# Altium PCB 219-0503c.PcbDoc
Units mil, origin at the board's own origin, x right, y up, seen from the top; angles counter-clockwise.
Board outline 5500 x 3800 mil, 2 copper layers (Top Layer, Bottom Layer); 110 components, 92 nets, 333 pads, 65 vias.
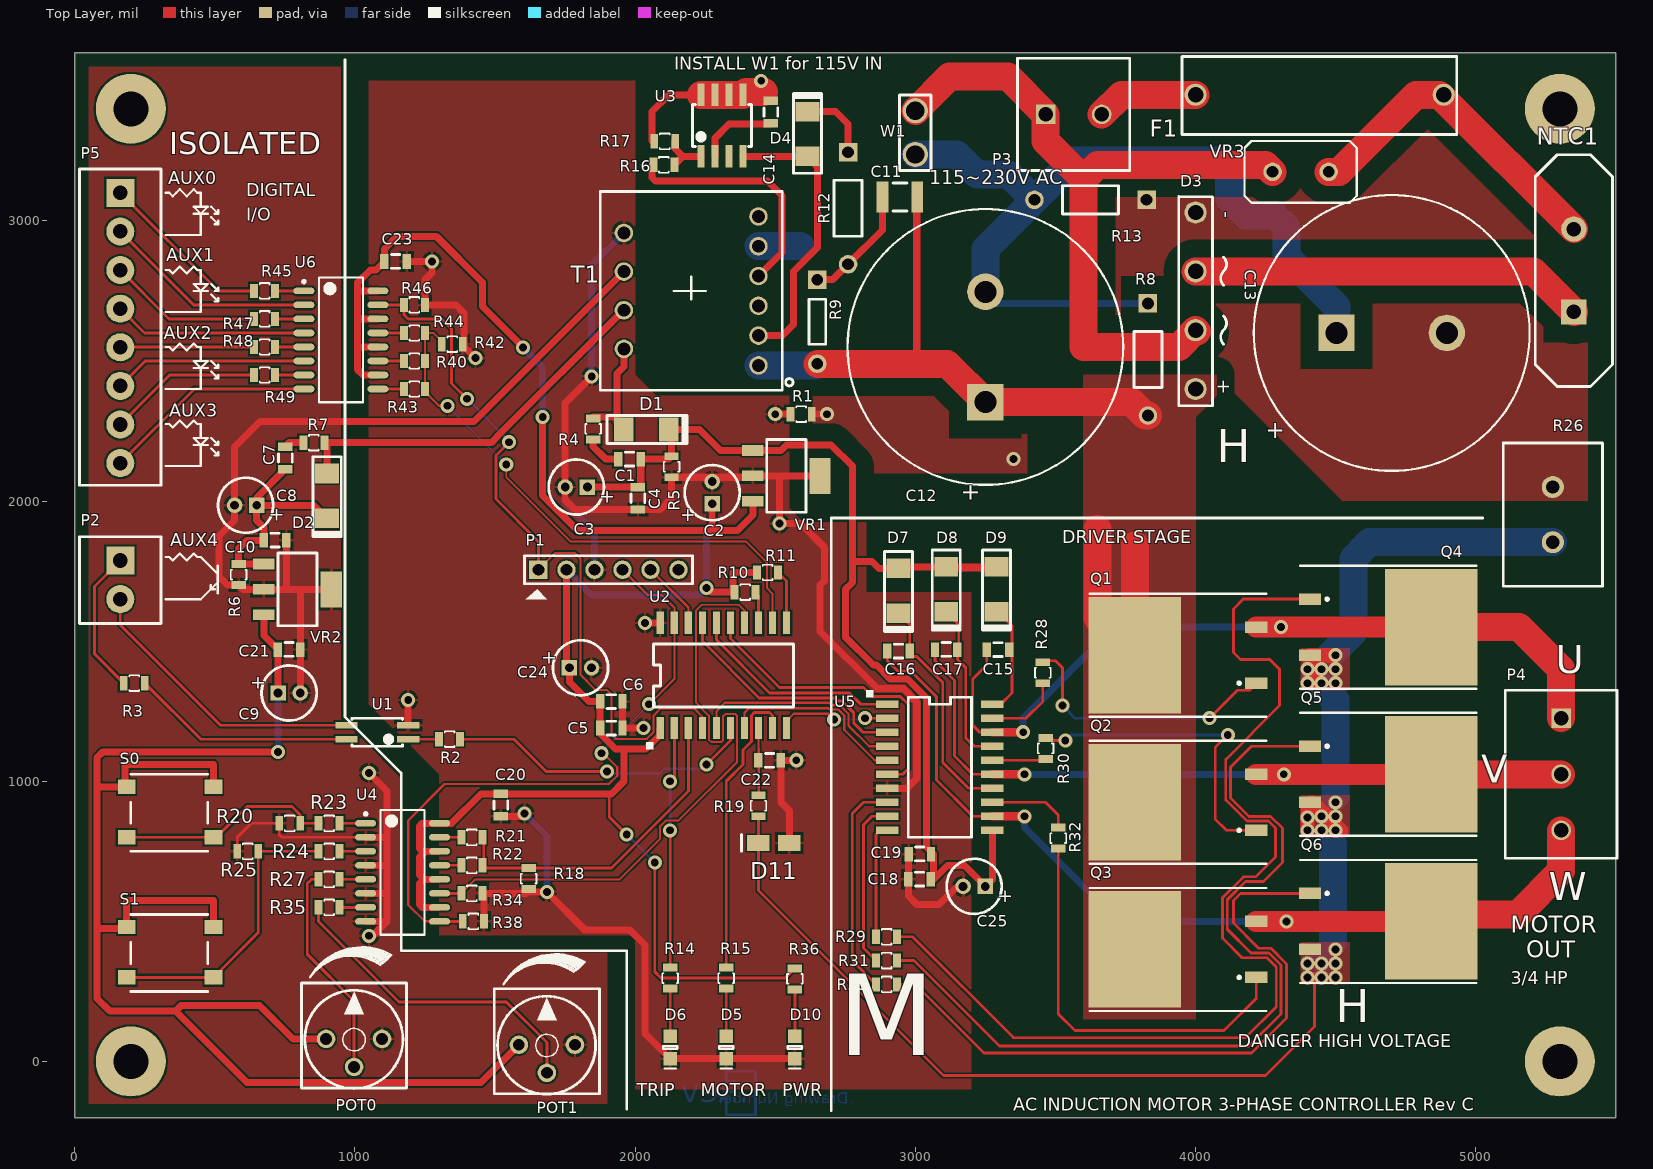
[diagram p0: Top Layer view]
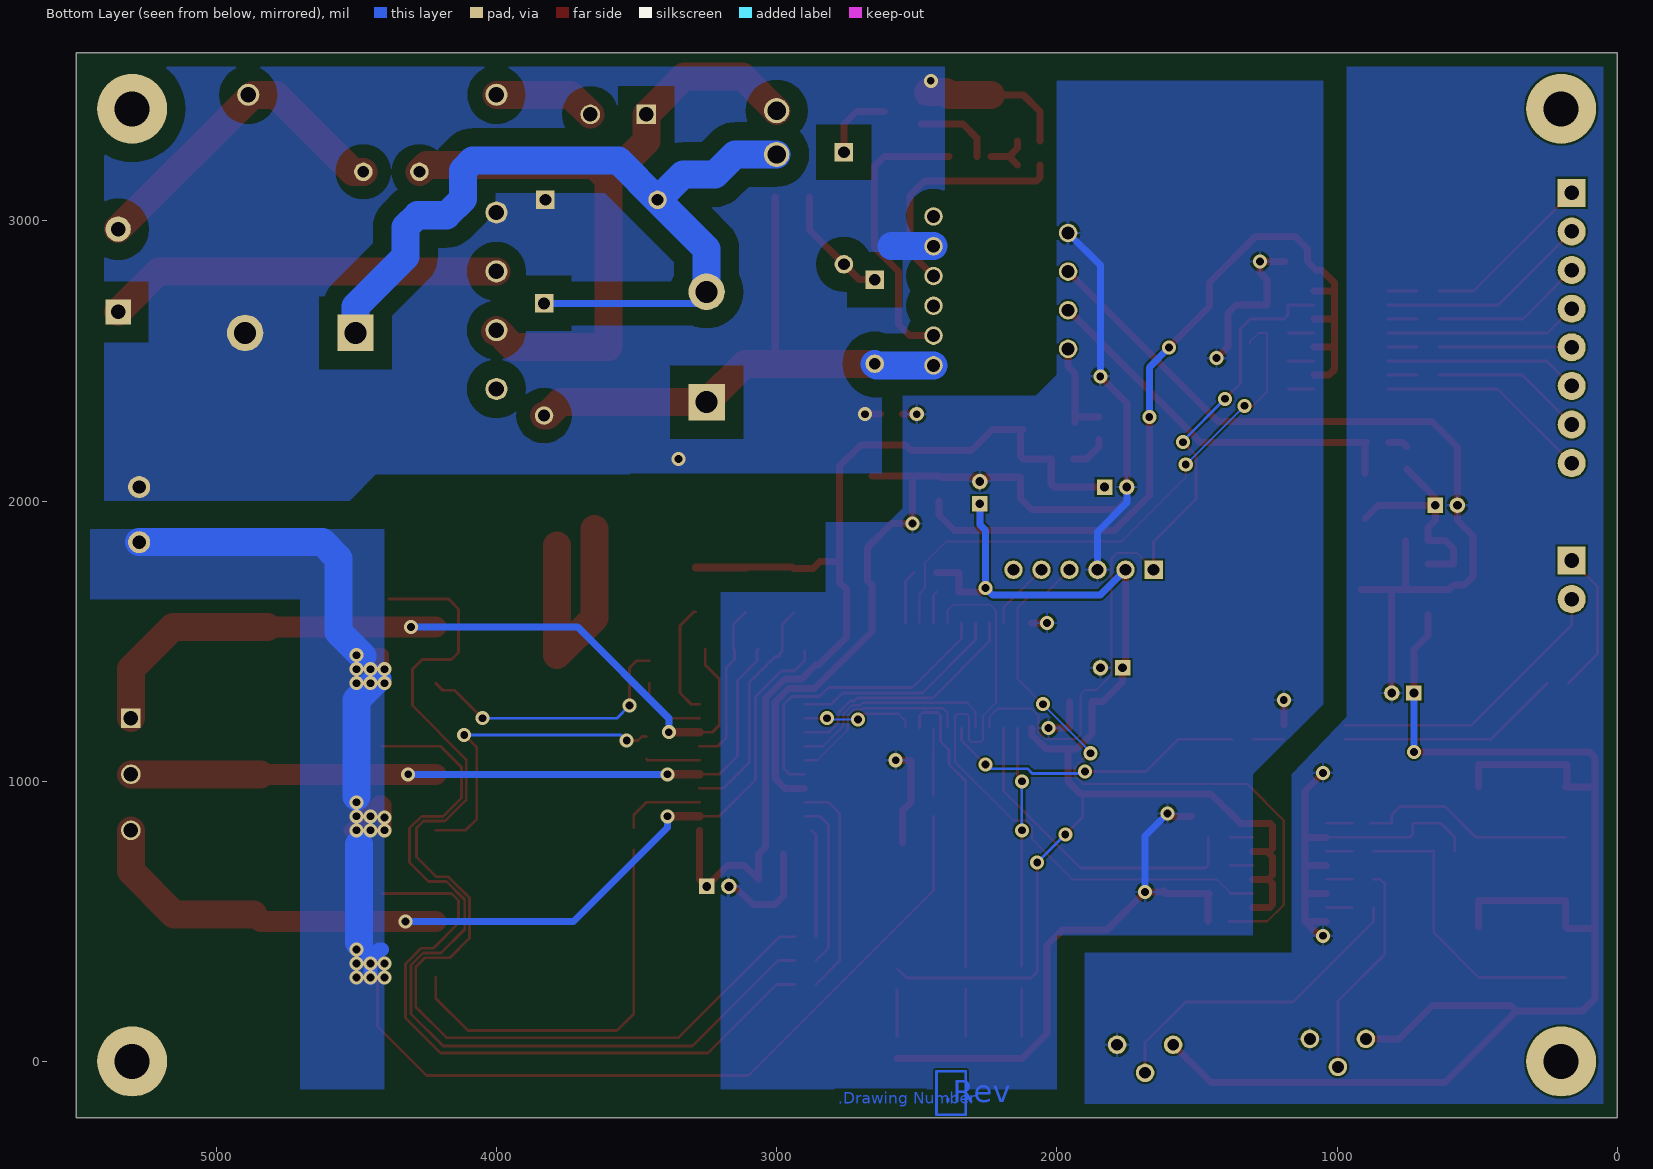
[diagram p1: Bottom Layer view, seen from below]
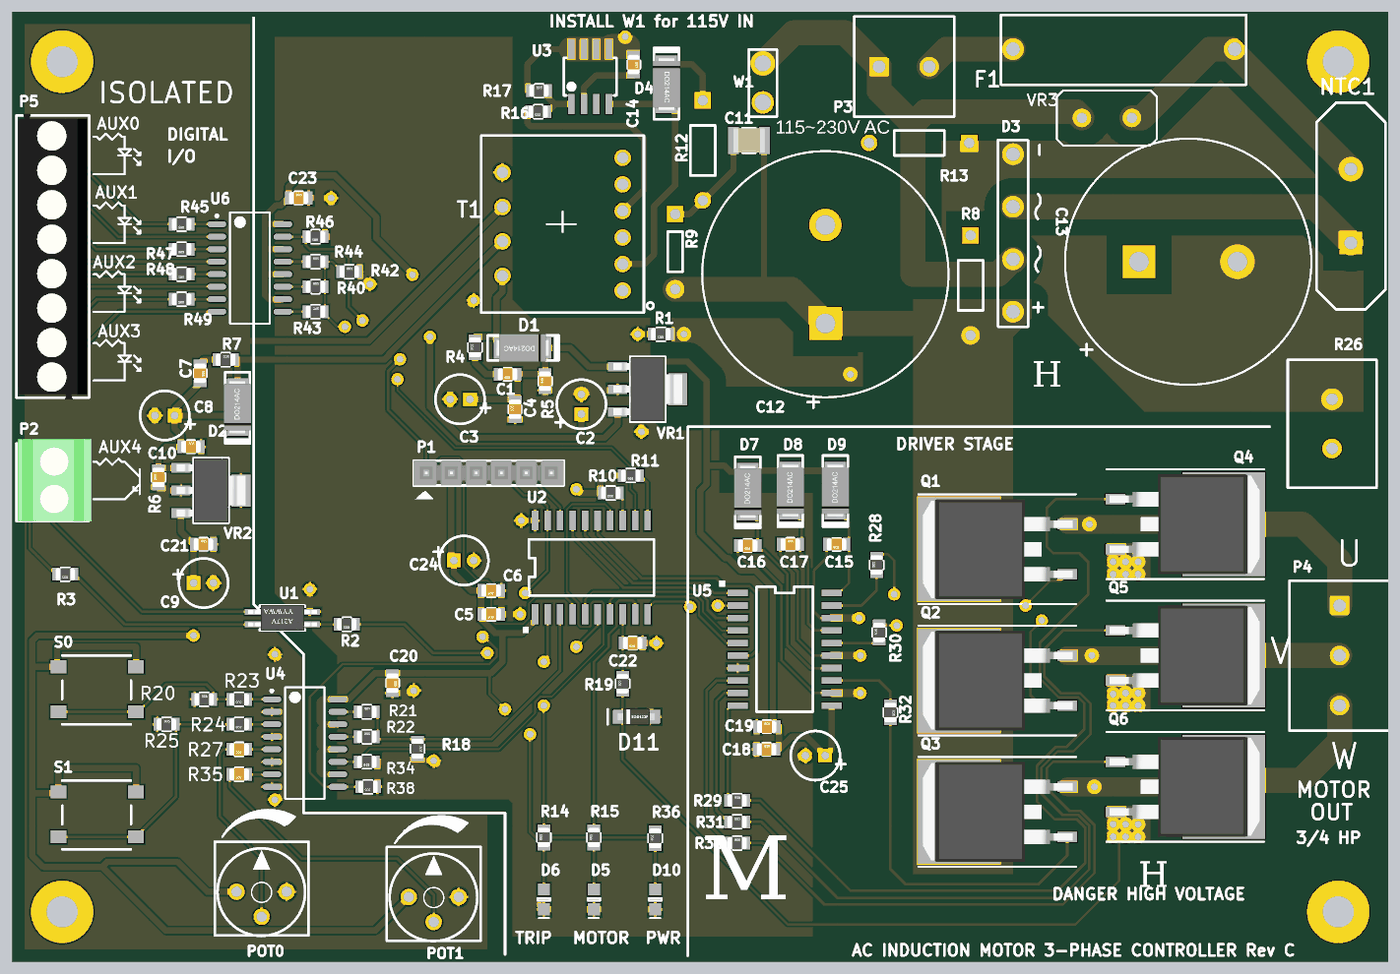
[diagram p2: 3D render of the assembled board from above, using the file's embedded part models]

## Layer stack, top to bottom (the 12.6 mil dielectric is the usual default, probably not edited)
Top Layer: signal copper 1.4
Dielectric: dielectric 12.6, FR-4, Dk 4.8
Bottom Layer: signal copper 1.4

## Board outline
0,-200 5500,-200 5500,3600 0,3600

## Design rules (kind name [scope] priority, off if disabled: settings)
Clearance Clearance_4 [InNamedPolygon('Top Layer-AGND')] p1: gap=65
Clearance Clearance_3 [InNamedPolygon('Bottom Layer-AGND')] p2: gap=65
Clearance [All] p3: gap=7
FabricationTestPointUsage TestPointUsage [All] p1: valid=0 allowmultiple=FALSE
FabricationTestpoint Testpoint [All] p1: side=3 testpointundercomponent=TRUE minsize=40 maxsize=100 preferedsize=60 minholesize=0 maxholesize=40 preferedholesize=32 testpointgrid=1 allowsidetop=TRUE allowsidebottom=TRUE usegrid=TRUE gridtolerance=0.01
HoleSize [All] p1: absolutevalues=TRUE maxlimit=125 minlimit=1 maxpercent=80.000 minpercent=20.000
PolygonConnect PolygonConnect_12 [All vs IsNamedPolygon('Top Layer-AGND')] p1: connectstyle=Direct reliefconductorwidth=10 reliefentries=4 polygonreliefangle="90 Angle" airgapwidth=10
PolygonConnect PolygonConnect_11 [All vs IsNamedPolygon('Bottom Layer-AGND')] p2: connectstyle=Direct reliefconductorwidth=10 reliefentries=4 polygonreliefangle="90 Angle" airgapwidth=10
PolygonConnect PolygonConnect_5 [All vs IsNamedPolygon('Top Layer-NetQ4_3')] p3: connectstyle=Direct reliefconductorwidth=10 reliefentries=4 polygonreliefangle="90 Angle" airgapwidth=10
PolygonConnect PolygonConnect_4 [All vs IsNamedPolygon('Top Layer-+VBUS')] p4: connectstyle=Direct reliefconductorwidth=10 reliefentries=4 polygonreliefangle="90 Angle" airgapwidth=10
PolygonConnect PolygonConnect_3 [All vs IsNamedPolygon('Top Layer-+VBUS')] p5: connectstyle=Direct reliefconductorwidth=10 reliefentries=4 polygonreliefangle="90 Angle" airgapwidth=10
PolygonConnect PolygonConnect_2 [All vs IsNamedPolygon('Bottom Layer-+VBUS')] p6: connectstyle=Direct reliefconductorwidth=10 reliefentries=4 polygonreliefangle="90 Angle" airgapwidth=10
PolygonConnect PolygonConnect_1 [All vs IsNamedPolygon('Bottom Layer-NetQ4_3')] p7: connectstyle=Direct reliefconductorwidth=10 reliefentries=4 polygonreliefangle="90 Angle" airgapwidth=10
PolygonConnect PolygonConnect_10 [All vs IsNamedPolygon('Bottom Layer-NetQ4_3')] p8: connectstyle=Direct reliefconductorwidth=10 reliefentries=4 polygonreliefangle="90 Angle" airgapwidth=10
PolygonConnect PolygonConnect_9 [All vs IsNamedPolygon('Bottom Layer-+VBUS')] p9: connectstyle=Direct reliefconductorwidth=10 reliefentries=4 polygonreliefangle="90 Angle" airgapwidth=10
PolygonConnect PolygonConnect_8 [All vs IsNamedPolygon('Bottom Layer-+VBUS')] p10: connectstyle=Direct reliefconductorwidth=10 reliefentries=4 polygonreliefangle="90 Angle" airgapwidth=10
PolygonConnect PolygonConnect_7 [All vs IsNamedPolygon('Top Layer-+VBUS')] p11: connectstyle=Direct reliefconductorwidth=10 reliefentries=4 polygonreliefangle="90 Angle" airgapwidth=10
PolygonConnect PolygonConnect_6 [All vs IsNamedPolygon('Bottom Layer-Net 1')] p12: connectstyle=Relief reliefconductorwidth=10 reliefentries=4 polygonreliefangle="90 Angle" airgapwidth=10
PolygonConnect [All] p13: connectstyle=Relief reliefconductorwidth=10 reliefentries=4 polygonreliefangle="90 Angle" airgapwidth=10
RoutingVias [All] p1: holewidth=28 width=50 viastyle="Through Hole" minholewidth=28 minwidth=50 maxholewidth=28 maxwidth=50
SilkToSolderMaskClearance SilkscreenOverComponentPads [IsPad] p1: minsilkscreentomaskgap=10 clearancetoexposedcopper=TRUE
SolderMaskExpansion [All] p1: expansion=4
Width [All] p1: maxlimit=100 minlimit=6 preferedwidth=10
24 further rules are at their usual default settings.

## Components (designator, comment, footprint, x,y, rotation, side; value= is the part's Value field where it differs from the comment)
C1 "CAP0805_470pF" CAP_0805 1980,2150 r180 top
C2 "UVZ1E100MDD" CAP079in_5mm 2275,2030 r90 top
C3 "ESH476M035AE3AA" CAP079in_5mm 1790,2050 r180 top
C4 "CAP0805_0.1uF_50V" CAP_0805 2010,2010 r90 top
C5 "CAP0805_0.1uF_50V" CAP_0805 1915,1190 r180 top
C6 "CAP0805_1uF" CAP_0805 1915,1285 r180 top
C7 "CAP0805_470pF" CAP_0805 751,2154 r270 top
C8 "ESH476M035AE3AA" CAP079in_5mm 610,1985 r180 top
C9 "UVZ1E100MDD" CAP079in_5mm 765,1315 r0 top
C10 "CAP0805_0.1uF_50V" CAP_0805 715,1860 r0 top
C11 "CAP1210_820pF" CAP_1210 2945,3085 r0 top
C12 "CAP_560uF_250V" CAPPRS10-25x50 3250,2550 r90 top
C13 "CAP_560uF_250V" CAPPRS10-25x50 4700,2600 r0 top
C14 "CAP0805_1uF" CAP_0805 2484,3388 r270 top
C15 "CAP0805_1uF" CAP_0805 3295,1470 r180 top
C16 "CAP0805_1uF" CAP_0805 2940,1465 r180 top
C17 "CAP0805_1uF" CAP_0805 3110,1470 r0 top
C18 "CAP0805_0.1uF_50V" CAP_0805 3015,650 r0 top
C19 "CAP0805_1uF" CAP_0805 3016,740 r0 top
C20 "CAP0805_1uF" CAP_0805 1520,915 r270 top
C21 "CAP0805_1uF" CAP_0805 765,1470 r0 top
C22 "CAP0805_1uF" CAP_0805 2480,1075 r180 top
C23 "CAP0805_1uF" CAP_0805 1145,2855 r0 top
C24 "UVZ1E100MDD" CAP079in_5mm 1805,1405 r0 top
C25 "UVZ1E100MDD" CAP079in_5mm 3210,625 r180 top
D1 "DIODE-SMA_STTH1L06A" DIODE-SMA 2120,2255 r270 top
D2 "DIODE-SMA_STTH1L06A" DIODE-SMA 900.79,1938.29 r180 top
D3 "Bridge1" DiodeBridge 4000,2400 r90 top
D4 "DIODE-SMA_STTH1L06A" DIODE-SMA 2615,3390 r0 top
D5 "LED2" LED_0805_RED 2325,50 r90 top
D6 "LED2" LED_0805_GRN 2125,50 r90 top
D7 "DIODE-SMA_STTH1L06A" DIODE-SMA 2940,1600 r180 top
D8 "DIODE-SMA_STTH1L06A" DIODE-SMA 3110,1605 r180 top
D9 "DIODE-SMA_STTH1L06A" DIODE-SMA 3290,1605 r180 top
D10 "LED2" LED_0805_GRN 2570.01,50 r90 top
D11 "CFRMT107-HF" TC3216 2550,780 r180 top
F1 "Fuse 2" FuseSocketHolder 4000,3450 r0 top
NTC1 "MF72-010D11" THERM_NTC_7.5MM_THERM_NTC_7.5MM(Primary) 5350,2675 r90 top
P1 "PICKIT2" TERMSTRIP_TSW-106-07-F-S 1905,1755 r0 top
P2 "ED555/2DS" "TERM BLOCK, 2POS, 3.81.mm" 162.5,1787.8 r0 top
P3 "OSTTC022162" 2PHDR-200 3465,3380 r90 top
P4 "EDZ350/3" 3PHDRX200 5305,1225 r0 top
P5 "Term_BLK_8pos 3.5mm" "TERM BLOCK, 8POS, 3.5mm" 162.5,3100 r0 top
POT0 "3386P-1-202TLF" POT3386P-1-XXXT 897,-107 r0 top
POT1 "3386P-1-202TLF" POT3386P-1-XXXT 1585,-128 r0 top
Q1 "IRG4BC20KD-S_1" D2PAK 4000,1450 r90 top
Q2 "IRG4BC20KD-S_1" D2PAK 4000,925 r90 top
Q3 "IRG4BC20KD-S_1" D2PAK 4000,400 r90 top
Q4 "IRG4BC20KD-S_1" D2PAK 4625,1550 r270 top
Q5 "IRG4BC20KD-S_1" D2PAK 4625,1025 r270 top
Q6 "IRG4BC20KD-S_1" D2PAK 4625,500 r270 top
R1 "RES_RC0805" RC_0805 2630,2310 r180 top
R2 "RES_RC0805" RC_0805 1375,1150 r180 top
R3 "RES_RC0805" RC_0805 250,1350 r180 top
R4 "RES_RC0805" RC_0805 1850,2220 r90 top
R5 "RES_RC0805" RC_0805 2130,2085 r90 top
R6 "RES_RC0805" RC_0805 585,1700 r90 top
R7 "RES_RC0805" RC_0805 815.79,2208.29 r0 top
R8 "CF14JT100K" RES400_RES400(Primary) 3830.28,2705.28 r270 top
R9 "RNMF14FTC270K" RES300_RES300(Primary) 2650,2790 r90 top
R10 "RES_RC0805" RC_0805 2430,1675 r180 top
R11 "RES_RC0805" RC_0805 2510,1745 r180 top
R12 "CF14JT330R" RES400_RES400(Primary) 2760,3245 r270 top
R13 "CF14JT100K" RES400_RES400(Primary) 3825,3075 r180 top
R14 "RES_RC0805" RC_0805 2125,260 r90 top
R15 "RES_RC0805" RC_0805 2325,260 r90 top
R16 "RMCF0805FT30K9" RC_0805 2140,3200 r180 top
R17 "RNCP0805FTD6K04" RC_0805 2068,3284 r0 top
R18 "RES_RC0805" RC_0805 1620,690 r270 top
R19 "RES_RC0805" RC_0805 2440,875 r90 top
R20 "RES_RC0805" RC_0805 730,850 r0 top
R21 "RES_RC0805" RC_0805 1380,800 r0 top
R22 "RES_RC0805" RC_0805 1380,700 r0 top
R23 "RES_RC0805" RC_0805 945,850 r180 top
R24 "RES_RC0805" RC_0805 945,750 r180 top
R25 "RES_RC0805" RC_0805 580,750 r0 top
R26 "2-1623788-5" "PowerResistor - 5W SQM 5MM Radial" 5275,2050 r270 top
R27 "RES_RC0805" RC_0805 945,650 r180 top
R28 "RES_RC0805" RC_0805 3455,1350 r90 top
R29 "RES_RC0805" RC_0805 2860,445 r0 top
R30 "RES_RC0805" RC_0805 3465,1080 r90 top
R31 "RES_RC0805" RC_0805 2860,360 r0 top
R32 "RES_RC0805" RC_0805 3510,835 r270 top
R33 "RES_RC0805" RC_0805 2860,275 r0 top
R34 "RES_RC0805" RC_0805 1455,600 r180 top
R35 "RES_RC0805" RC_0805 945,550 r180 top
R36 "RES_RC0805" RC_0805 2570.01,256.86 r90 top (schematic designator R15)
R38 "RES_RC0805" RC_0805 1460,500 r180 top
R40 "RES_RC0805" RC_0805 1175,2500 r0 top
R42 "RES_RC0805" RC_0805 1310,2560 r0 top
R43 "RES_RC0805" RC_0805 1175,2400 r0 top
R44 "RES_RC0805" RC_0805 1175,2600 r0 top
R45 "RES_RC0805" RC_0805 715,2750 r180 top
R46 "RMCF0805FT180R" RC_0805 1250,2700 r180 top
R47 "RES_RC0805" RC_0805 715,2650 r180 top
R48 "RES_RC0805" RC_0805 715,2550 r180 top
R49 "RES_RC0805" RC_0805 715,2450 r180 top
S0 "B3S-1002" SW-B3S1002 500,800 r180 top
S1 "B3S-1002" SW-B3S1002 500,300 r180 top
T1 "750813144" Trans_750813134 2200,2750 r90 top
U1 "ACPL-217-500E" so4_wstep 1190,1150 r180 top
U2 "PIC16F1509-I/SO" SO20 2090,1190 r90 top
U3 "LNK625DG" so8 2235,3230 r90 top
U4 "ACPL-247-500E" SOP127P762-16L 1170,675 r0 top
U5 "IRS2334SPbF" so20 2900,1275 r0 top
U6 "ACPL-247-500E" SOP127P762-16L 950,2575 r0 top
VR1 "MCP1703T-5002E/DB" SOT223-3 2420,2090 r270 top
VR2 "MCP1703T-5002E/DB" SOT223-3 675,1685 r270 top
VR3 "MOV_MOV-07D471K" MOV_ERZ-V07D431_MOV_ERZ-V07D431(Primary) 4475,3175 r180 top
W1 "286 SV001" HEADER_156sp_1X2_DNP 3000,3315 r270 top

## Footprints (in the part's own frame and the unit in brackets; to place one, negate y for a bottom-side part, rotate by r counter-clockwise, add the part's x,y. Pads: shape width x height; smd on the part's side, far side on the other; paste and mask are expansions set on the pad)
2PHDR-200 [mil]
  rect 70x70 hole 51.18: 1(0,0)
  round 70 hole 51.18: 2(0,-200)
  silkscreen extent -200,-300 200,100
3PHDRX200 [mil]
  rect 70x70 hole 51.18: 1(0,0)
  round 70 hole 51.18: 2(0,-200) 3(0,-400)
  silkscreen extent -200,-500 200,100
CAP079in_5mm [mm]
  rect 1.4x1.4 hole 0.8: 1(-1.003,0)
  round 1.4 hole 0.8: 2(1.003,0)
  silkscreen extent -2.5,-2.5 2.5,2.5
CAP_0805 [mil] "Cap, Chip, 0805(2012)"
  rect 30x52 smd: 1(-40,0) 2(40,0)
  silkscreen extent -15,-24 15,25, body extent -39,-25 39,25, height 31
CAP_1210 [mil]
  rect 42x110 smd: 1(-62,0) 2(62,0)
  silkscreen extent -25,-50 25,50, body extent -63,-49 63,49, height 30
CAPPRS10-25x50 [mm] "Capacitor, Electrolytic, Radial, Snap-In Pins; Body 25 x 50 mm (Dia.xH typ); Pin Spacing 10 mm (typ)"
  rect 3.3x3.3 hole 2: 1(-5,0)
  round 3.3 hole 2: 2(5,0)
  silkscreen extent -12.5,-12.5 12.5,12.5
D2PAK [mm] "D2-PAK/TO-263-AB; 3 Leads (1 Cropped); Body 15.5 (inc. leads) x 10.5 mm (LxW max)"
  rect 1.05x2 smd: 1(-2.54,-5.5) 3(2.54,-5.5)
  rect 10.55x8.4 smd: 2(0,5.5)
  silkscreen extent -5.58,-6.4 5.58,9.6, body extent -5.08,-6.11 5.08,9.16, height 4.92
DIODE-SMA [mil]
  rect 85x70 smd: 1(0,0) 2(0,-160)
  silkscreen extent -50,-220 50,65, body extent -55,-188 55,28, height 90
DiodeBridge [mm] "10A MCC Diode Bridge"
  round 2 hole 1.4: 1(0,0) 2(5.33,0) 3(10.66,0) 4(16,0)
  silkscreen extent -1.52,-2.8 17.45,1.52, body extent -1.55,-1.6 17.4,1.55, height 18
FuseSocketHolder [mm] "FUSEHOLDER OGD 5X20/6.3X32MM SMD"
  round 2 hole 1.4: 1(0,0) 2(22.5,0)
  silkscreen extent -1.22,-3.61 23.67,3.48
HEADER_156sp_1X2_DNP [mil] "1 X 2 HEADER, UNPOPULATED .156 Spacing"
  round 90 hole 65: 1(-78,0) 2(78,0)
  silkscreen extent -134,-56 135,56
LED_0805_GRN [mil]
  rect 48x48 smd mask+4: 1(-40,0) 2(40,0)
  silkscreen extent -75,-25 5,25, body extent -40,-25 40,25, height 43
LED_0805_RED [mil] "LED, SMD, 0805 package"
  rect 48x48 smd mask+4: 1(-40,0) 2(40,0)
  silkscreen extent -75,-25 5,25, body extent -40,-25 40,25, height 43
MOV_ERZ-V07D431_MOV_ERZ-V07D431(Primary) [mil]
  round 66 hole 42: A(0,0) B(200,0)
  silkscreen extent -100,-110 300,110
POT3386P-1-XXXT [mil]
  round 66 hole 42: 1(0,187.5) 2(100,87.5) 3(200,187.5)
  silkscreen extent -88,11 288,388
"PowerResistor - 5W SQM 5MM Radial" [mm] "5W SQM Vertical Power Resistor"
  round 2 hole 1.2: 1(0,0) 2(5,0)
  silkscreen extent -4,-4.5 9,4.5
RC_0805 [mil]
  rect 28x51 smd: 1(0,0) 2(75,0)
  silkscreen extent 20,-28 55,28, body extent -2,-25 77,25, height 31
RES300_RES300(Primary) [mil]
  rect 66x66 hole 42: A(0,0)
  round 66 hole 42: B(-300,0)
  silkscreen extent -230,-30 -70,30
RES400_RES400(Primary) [mil]
  rect 66x66 hole 42: A(0,0)
  round 66 hole 42: B(400,0)
  silkscreen extent 100,-50 300,50
so4_wstep [mil]
  rect 80x23.62 smd: 1(0,0) 2(0,-50) 3(220,-50) 4(220,0)
  silkscreen extent 20,-75 200,25, body extent -28,-76 248,26, height 82
so8 [mil]
  rect 80x26 smd: 1(0,0) 2(0,-50) 3(0,-100) 4(0,-150) 5(220,-150) 6(220,-100) 7(220,-50) 8(220,0)
  silkscreen extent 35,-180 185,30
SO20 [mil]
  rect 80x26 smd: 1(0,0) 2(0,-50) 3(0,-100) 4(0,-150) 5(0,-200) 6(0,-250) 7(0,-300) 8(0,-350) 9(0,-400) 10(0,-450) 11(375,-450) 12(375,-400) 13(375,-350) 14(375,-300) 15(375,-250) 16(375,-200) 17(375,-150) 18(375,-100) 19(375,-50) 20(375,0)
  silkscreen extent -75,-475 300,50
so20 [mil]
  rect 80x26 smd: 1(0,0) 2(0,-50) 3(0,-100) 4(0,-150) 5(0,-200) 6(0,-250) 7(0,-300) 8(0,-350) 9(0,-400) 10(0,-450) 11(375,-450) 12(375,-400) 13(375,-350) 14(375,-300) 15(375,-250) 16(375,-200) 17(375,-150) 18(375,-100) 19(375,-50) 20(375,0)
  silkscreen extent -75,-475 300,50
SOP127P762-16L [mm] "16-Pin Small Outline Package 1.27 mm Pitch"
  oval 1.9x0.6 smd: 1(-3.35,4.445) 2(-3.35,3.175) 3(-3.35,1.905) 4(-3.35,0.635) 5(-3.35,-0.635) 6(-3.35,-1.905) 7(-3.35,-3.175) 8(-3.35,-4.445) 9(3.35,-4.445) 10(3.35,-3.175) 11(3.35,-1.905) 12(3.35,-0.635) 13(3.35,0.635) 14(3.35,1.905) 15(3.35,3.175) 16(3.35,4.445)
  silkscreen extent -3.47,-5.65 2,5.65, body extent -2.85,-5.65 2.85,5.65, height 2.2
SOT223-3 [mil]
  rect 38x76 smd mask+4: 1(-90.5,0) 2(0,0) 3(90.5,0)
  rect 128x76 smd mask+4: 4(0,240)
  silkscreen extent -130,50 130,190, body extent -128,-18 128,258, height 64
SW-B3S1002 [mm]
  rect 1.6x1.3 smd: 1(0.127,0) 2(8.001,0) 3(0.127,-4.572) 4(8.001,-4.572)
  silkscreen extent 0.63,-5.71 7.62,1.27
TC3216 [mil]
  rect 80x56 smd: 1(0,0) 2(110,0)
  silkscreen extent 170,-30 170,30, body extent -18,-33 130,33, height 47
"TERM BLOCK, 2POS, 3.81.mm" [mil] "TERM BLOCK 2POS 3.81MM PCB"
  rect 100x100 hole 52: 1(0,0)
  round 100 hole 52: 2(0,-137.8)
  silkscreen extent -146,-225 146,85, body extent -140,-227 156,103, height 396
"TERM BLOCK, 8POS, 3.5mm" [mil] "TERM BLOCK 8POS 3.5MM PCB"
  rect 100x100 hole 52: 1(0,0)
  round 100 hole 52: 2(0,-137.8) 3(0,-275.59) 4(0,-413.39) 5(0,-551.18) 6(0,-688.98) 7(0,-826.77) 8(0,-964.57)
  silkscreen extent -146,-1043 146,85, body extent -138,-1050 138,92, height 331
TERMSTRIP_TSW-106-07-F-S [mil] "Terminal Strip, 1 X 6, 0.100sp, 0.025 sq post"
  rect 66x66 hole 42: 1(-250,0)
  round 66 hole 42: 2(-150,0) 3(-50,0) 4(50,0) 5(150,0) 6(250,0)
  silkscreen extent -300,-50 300,50, body extent -300,-50 300,50, height 330
THERM_NTC_7.5MM_THERM_NTC_7.5MM(Primary) [mil]
  rect 90x90 hole 52: 1(0,0)
  round 90 hole 52: 2(295.28,0)
  silkscreen extent -266,-138 561,138
Trans_750813134 [mil] "TRANSFORMER FLYBACK LT3799"
  round 66 hole 46: 1(-265.75,-240.16) 2(-159.45,-240.16) 3(-53.15,-240.16) 4(53.15,-240.16) 5(159.45,-240.16) 6(265.75,-240.16) 7(206.69,240.16) 8(68.9,240.16) 9(-68.9,240.16) 10(-206.69,240.16)
  silkscreen extent -354,-363 354,325

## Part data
C1 C7: "CAP CER 470PF 100V 5% NP0 0805"
C2 C9 C24 C25: library part CAP100RP_10uF_25V, "CAP ALUM 10UF 25V 20% RADIAL"
C3 C8: library part CAP100RP_47uF_35V, "CAP ALUM 47UF 35V 20% RADIAL"
C4 C5 C10 C18: "Cap, Ceramic, 0.1uF, 50V X7R"
C6 C14 C15 C16 C17 C19 C20 C21 C22 C23: "CAP CER 1UF 50V 10% X5R 080"
C11: "CAP CER 820PF 2KV 10% X7R 1210"
C12 C13: "CAP ALUM 560UF 250V 20% SNAP"
D1 D2 D4 D7 D8 D9: "DIODE ULTRA FAST 600V 1A SMA"
D3: "Full Wave Diode Bridge"
D5: library part LED_0805_YEL, "LED, SMD, YEL, 0805 package"
D6 D10: library part LED_0805_GRN, "LED, SMD, GRN, 0805 package"
D11: library part DIODE_FAST_SOD123, "DIODE_FAST_SOD123"
F1: "FUSEHOLDER 22.5MM PCB 5X20MM BK"
NTC1: library part THERM_NTC_MF72-010D11, "Current Limiter Inrush 100R 20%"
P1: library part HEADER_1X6_PICKIT2, "Header, Pickit2, 1X6 0.1sp"
P2: library part HDR_TERM_BLK3.5mm2POS, "TERMINAL BLOCK 3.5MM 2POS PCB"
P3: library part 2PHDR-200, "2PHDR-200"
P4: library part HDR_TERM_BLK5.08mm3POS, "TERMINAL BLOCK 5.08MM 3POS PCB"
POT0 POT1: library part POT-3386P-1-202TLF
Q1 Q2 Q3 Q4 Q5 Q6: "Insulated Gate Bipolar Transistor with Ultrafast Soft Recovery Diode"
R1 R3: library part RES_RC0805_0R, "RES 0.0 OHM 1/8W 0805 SMD"
R2 R45 R47 R48 R49: library part RES_RC0805_510R, "RES 510 OHM 1/8W 0805 SMD"
R4 R7: library part RES_RC0805_47R, "RES 47 OHM 1/8W 0805 SMD"
R5 R6: library part RES_RC0805_820R, "RES 820 OHM 1/8W 0805 SMD"
R8 R13: library part RES400_100K, "RES 100K OHM 1/4W 5% CARBON FILM"
R9: library part RES300_270K, "RES 270K OHM 1/4W 5% CARBON FILM"
R10 R11: library part RES_RC0805_4.7K, "RES 4.7K OHM 1/8W 1% 0805 SMD"
R12: library part RES400_330R, "RES 330 OHM 1/4W 5% CARBON FILM"
R14 R15 R23 R24 R36: library part RES_RC0805_1K, "RES 1K OHM 1/8W 1% 0805 SMD"
R16: library part RES_RC0805_30.9K, "RES 30.9K OHM 1/8W 1% 0805 SMD"
R17: library part RES_RC0805_6.04K, "RES 6.04K OHM 1/8W 1% 0805 SMD"
R18 R20 R25 R40 R42: library part RES_RC0805_10K, "RES 10K OHM 1/8W 1% 0805 SMD"
R19: library part RES_RC0805_160K, "RES 160K OHM 1/8W 1% 0805 SMD"
R21 R27 R34 R35 R38 R43: library part RES_RC0805_390R, "RES 390 OHM 1/8W 0805 SMD"
R22 R44: library part RES_RC0805_5.1K, "RES 5.1K OHM 1/8W 1% 0805 SMD"
R26: library part Res_5W_0R22vertical, "RES 0.22 OHM 5W 5% RADIAL"
R28 R29 R30 R31 R32 R33: library part RES_RC0805_20R, "RES 20 OHM 1/8W 1% 0805 SMD"
R46: library part RES_RC0805_180R, "RES 180 OHM 1/8W 1% 0805 SMD"
S0 S1: library part SW-B3S1002, "SWITCH TACTILE SPST-NO 0.05A 24V"
T1: library part Trans_750813144, "Four-winding Transformer (Non-Ideal)"
U1: library part Opto_ACPL-217-500E, "4-Pin Phototransistor Optocoupler"
U2: "8-bit Micro"
U3: "AC/DC converter"
U4 U6: library part Optoisolator_ACPL-247-500E, "ISOLATOR 3KVRMS 4CH TRANS 16SOI"
U5: "IC MOSFET DRIVER"
VR1 VR2: "High Voltage Regulator, 5V, 70mA, SOT-223"
VR3: library part MOV_ERZ-V07D431, "Resistor"
W1: library part "Jumper_156\"sp_DNP", "Jumper Wire"

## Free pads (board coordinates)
  round 250 hole 125: 0(200,3400) 1(200,0) 2(5300,3400) 3(5300,0)

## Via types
v1: diameter 50, hole 28, Top Layer to Bottom Layer, 65 vias

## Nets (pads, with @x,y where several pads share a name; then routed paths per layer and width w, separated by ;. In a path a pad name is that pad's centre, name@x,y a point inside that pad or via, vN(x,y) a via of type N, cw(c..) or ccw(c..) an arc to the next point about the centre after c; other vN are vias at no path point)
+5V: C2.1 C5.2 C6.2 C20.1 C23.1 C24.1 P1.2 R10.2 R11.2 R36.2 U2.1 U4.10 U4.12 U4.14 U4.16 U6.10 U6.12 U6.14 U6.16 VR1.3 | length 7703.2
  Top Layer w10: 1907.5,947.5 1907.5,872.5 v1(1970,810) ; v1(2070,710) 2070,320 2092.5,297.5 2535.65,297.5 R36.2
  Top Layer w25: U6.10 1028.74,2450 1010,2468.74 1010,2550 ; U6.12 1010,2550 ; U6.14 1010,2650 ; U6.16 1010,2750 ; 1240,750 1230,760 1230,840 1240,850 U4.16 1345,850 1450,955 C20.1 1915,955 1959.5,999.5 1959.5,1110.5 1955,1115 ; U4.10 1240,550 1230,560 1230,635 1245,650 ; U4.12 1245,650 ; U4.14 1250,750 1230,730 1230,665 1245,650 ; v1(1600,2547.5) 1600,2550 1455,2695 1455,2780 1290,2945 1150,2945 1105,2900 C23.1 1075,2825 1055,2825 1010,2780 1010,2750 ; v1(1670,2300) 1670,2020 1794.21,1895.79 2255,1895.79 ; P1.2 1755,1420.5 C24.1@1770.5,1405 ; C24.1 1765.5,1354.5 1835,1285 C6.2 C5.2 1875,1170 1930,1115 1955,1115 ; U2.1 2088.5,1188.5 2088.5,1165.77 2037.73,1115 1955,1115 ; v1(2255,1690) 2270,1675 2350,1675 2350,1745 R11.2@2430,1745 ; 2255,1895.5 2275,1895.5 ; C2.1 2275,1895.5 ; VR1.3 2420,1950 2365.5,1895.5 2275,1895.5 ; 1010,2550 1010,2650 ; 1010,2650 1010,2750
  Bottom Layer w10: v1(1970,810) v1(2070,710)
  Bottom Layer w25: v1(1600,2547.5) 1670,2477.5 v1(1670,2300) ; P1.2 1845,1665 2230,1665 v1(2255,1690) 2255,1895.79 2275,1915.79 C2.1
"+5V ISO": C9.1 C21.1 POT0.1 POT1.1 S0.3 S0.4 S1.3 S1.4 VR2.3 | length 5494.9
  Top Layer w25: S1.3 495,575 185,575 S1.4 180,475 80,475 ; S0.3 495,1060 180,1060 180,985 S0.4 85,980 80,985 ; VR2.3 675,1520 C21.1 725,1315.5 C9.1 ; v1(725,1105) 100,1105 80,1085 80,985 ; POT0.1 779.5,80.5 660,200 380,200 360,180 ; POT1.1 1450.5,-75 615,-75 360,180 ; 80,475 80,985 ; 80,475 80,225 125,180 360,180
  Bottom Layer w25: v1(725,1105) 725.5,1105.5 C9.1
+15V: C1.1 C3.1 C4.2 C18.2 C19.2 C25.1 D1.1 D7.2 D8.2 D9.2 R5.2 U5.11 VR1.1 | length 4024.4
  Top Layer w25: C3.1@1834.21,2050 C4.2 2020,2060 C1.1 2120,2150 R5.2 D1.1@2130,2245 ; D1.1 D1.1@2130,2245 ; D7.2 2870,1760 2845,1785 2775,1785 ; D7.2@2945,1765 D8.2 D9.2 ; D8.2@3110,1762 D9.2@3290,1762 ; U5.11 3275,650 3250,625 3175,700 3115,700 3065,650 3065,740 3040,765 3040,1297.6 2972.1,1365.5 2910.29,1365.5 2861.29,1414.5 2850.68,1414.5 2750,1515.18 2750,1685 2775,1710 2775,1785 ; D1.1@2130,2245 2130,2255 2230,2255 2304.5,2180.5 VR1.1 2520.01,2180.5 2540,2200.49 2699.51,2200.49 2775,2125 2775,1785
+VBUS: C11.2 C12.1 D3.1 Q1.2 Q2.2 Q3.2 R8.B R9.B T1.1 | length 2960.8
  Top Layer w25: 3005,2490 C11.2@3005,3085
  Top Layer w100: R9.B 3005,2490 3113.15,2490 C12.1 3771.85,2353.15 3819.72,2305.28 R8.B ; 3650,1900 3650,1583.46 Q1.2 3783.46,1841.54
  Bottom Layer w100: T1.1 2644.25,2484.25 R9.B
AGND: C13.2 C14.1 D3.4 R1.1 R13.A R17.1 R26.1 T1.5 U3.5 U3.6 U3.7 U3.8 | length 780.2
  Top Layer w25: R17.1@2060,3285 2060,3390 2120,3450 U3.8 ; 2460,3460 2484,3436 C14.1 ; R1.1 v1(2685,2310)
  Top Layer w100: U3.8 U3.7 U3.6 U3.5 2395,3460 2460,3460
  Bottom Layer w100: T1.5 2589.45,2909.45
  other v1: 3350,2150 2450,3500
AUX1: R40.2 R42.1 R43.2 R44.2 U2.12 | length 2015.1
  Top Layer w7: R42.1 1310,2570 1280,2600 R44.2 R40.2 R43.2 1250,2390 1300,2340 v1(1330,2340) ; v1(1540,2130) 1540,2085 1770,1855 2395.69,1855 2470.69,1780 2470.69,1689.31 2490,1670 U2.12
  Bottom Layer w7: v1(1330,2340) v1(1540,2130)
CLC1: U2.17 U5.3 | length 880.9
  Top Layer w10: U2.17 2240,1500 2442.5,1297.5 2712.5,1297.5 2723,1287 2737.75,1287 2780,1244.75 2780,1208.43 2813.43,1175 U5.3
CLC2: U2.16 U5.1 | length 765.3
  Top Layer w10: U2.16 2290,1505 2480,1315 2765,1315 2805,1275 U5.1
CLC3: U2.10 U5.2 | length 406.5
  Top Layer w8: U2.10 2540,1215 2566,1241 2689,1241 v1(2710,1220) ; v1(2820,1225) U5.2
  Bottom Layer w8: v1(2710,1220) 2815,1220 v1(2820,1225)
DGND: C2.2 C3.2 C4.1 C5.1 C6.1 C18.1 C19.1 C20.2 C22.1 C23.2 C24.2 C25.2 D5.1 D6.1 D10.1 D11.1 P1.3 R1.2 R5.1 R18.2 R34.1 R38.1 R42.2 R46.1 T1.7 U1.2 U2.20 U5.7 VR1.2 VR1.4 | length 7662.1
  Top Layer w25: C23.2 v1(1275,2855) 1275,2815 1250,2790 R46.1 1360,2700 1390,2670 1390,2550 v1(1430,2510) ; U1.2 v1(1190,1290) ; R38.1 1460,595 R34.1 1610,600 1620,610 1625,605 v1(1685,605) 1820,470 1980,470 2035,415 2035,100 D6.1 D5.1 D10.1 ; C20.2@1520.06,875.57 1520,875.5 C20.2 1595,875 v1(1605,885) ; v1(1845,2445) 1750.5,2350.5 C3.2 1750.5,2004.5 1785,1970 2090,1970 2130,2010 R5.1 2415,2085 VR1.2 2515,2090 ; C6.1 C5.1 v1(2030,1190) ; v1(2035,1565) U2.20 ; v1(2500,2310) R1.2@2550,2310 ; D11.1 2550,895 2520,925 C22.1 v1(2575,1075) ; VR1.4 2515,2090 ; U5.7 2970,975 3005,1010 3005,1283.1 2957.6,1330.5 2864.5,1330.5 2660,1535 2660,1700 2675,1715 2675,1835 2590,1920 v1(2515,1920) 2515,2090 ; C19.1@2975,740 C18.1 2975,590 3005,560 3085,560 C25.2@3150,625
  Bottom Layer w25: v1(1605,885) 1685,805 v1(1685,605) ; C3.2@1735.79,2050 C3.2@1750.5,2035.29 ; C3.2 C3.2@1750.5,2035.29 ; v1(1845,2445) 1845,2841.85 T1.7 ; P1.3 1855,1890 1750.5,1994.5 C3.2@1750.5,2035.29
"GARAGE LIGHT": R2.1 U2.6 | length 1109
  Top Layer w10: R2.1 1567.58,1150 1682.58,1035 v1(1900,1035) ; v1(2255,1060) 2340,1145 U2.6
  Bottom Layer w10: v1(1900,1035) 1907,1028 2088,1028 2105,1045 2240,1045 v1(2255,1060)
HOT: F1.1 P3.2 | length 364
  Top Layer w100: P3.2 3735,3450 F1.1
ISENSE: C22.2 R19.2 U2.8 | length 345.1
  Top Layer w8: R19.2 2441,951 2441,1015 ; U2.8 2440,1016 2441,1015 ; 2441,1115 C22.2@2441,1078 ; C22.2@2444,1075 C22.2@2441,1078 ; 2441,1015 C22.2@2441,1078
ISOGND: C8.2 C9.2 C10.2 C21.2 POT0.3 POT1.3 R6.1 R20.1 R25.1 T1.8 U4.2 U4.4 U4.6 U4.8 VR2.2 VR2.4 | length 4622.2
  Top Layer w10: R25.1 580,800 630,850 R20.1 730,810 740,800 U4.2
  Top Layer w25: C10.2 755,1685 ; C9.2 805,1315.5 C21.2 805,1685 ; VR2.4 805,1685 ; U4.8 1115,500 ; U4.6 1115,600 ; U4.4 1115,700 ; U4.2 1115,800 ; v1(1050,448.62) 1063.62,448.62 1115,500 ; v1(1050,1030) 1115,965 1115,800 ; T1.8 1424.23,2283.29 660.79,2283.29 570.5,2193 C8.2 570.5,1930.5 515,1875 515,1730 545,1700 R6.1 600,1685 VR2.2 755,1685 ; 755,1685 805,1685 ; 1115,500 1115,600 ; 1115,600 1115,700 ; 1115,700 1115,800
M1: C15.2 P4.1 Q1.3 Q4.2 U5.18 | length 2911.3
  Top Layer w10: C15.2 3255,1415 3205,1365 3205,1200 3230,1175 U5.18
  Top Layer w30: U5.18 v1(3385,1175)
  Top Layer w75: Q1.3 v1(4305,1550) Q4.2@4816.54,1550
  Top Layer w100: Q4.2@4816.54,1550 5155,1550 5305,1400 P4.1
  Bottom Layer w25: v1(3385,1175) 3385,1225 3710,1550 v1(4305,1550)
M2: C17.1 P4.2 Q2.3 Q5.2 U5.15 | length 2706.5
  Top Layer w10: C17.1@3065,1470 C17.1@3070,1465 ; C17.1 C17.1@3070,1465 ; U5.15 3205,1025 3140,1090 3140,1360 3070,1430 C17.1@3070,1465
  Top Layer w30: U5.15 v1(3390,1025)
  Top Layer w75: Q2.3 v1(4315,1025) Q5.2
  Top Layer w100: Q5.2 P4.2
  Bottom Layer w25: v1(3390,1025) v1(4315,1025)
M3: C16.2 P4.3 Q3.3 Q6.2 U5.12 | length 3315
  Top Layer w10: C16.2 2900,1430 2937,1393 2983.49,1393 3075,1301.49 3075,1005 3205,875 U5.12
  Top Layer w30: U5.12 v1(3390,875)
  Top Layer w75: Q3.3 v1(4325,500) Q6.2
  Top Layer w100: Q6.2@4866.54,525 5150,525 5305,680 P4.3
  Bottom Layer w25: v1(3390,875) 3390,835 3725,500 v1(4325,500)
NetC1_2: C1.2 R4.1 | length 133.6
  Top Layer w25: R4.1 1850,2195 1895,2150 C1.2
NetC7_1: C7.1 R7.1 | length 70.7
  Top Layer w25: C7.1 765.29,2208.29 R7.1
NetC7_2: C7.2 C8.1 C10.1 D2.1 R6.2 VR2.1 | length 824
  Top Layer w25: C8.1 649.5,1930.5 675,1905 C10.1 615,1860 585,1830 R6.2 674.5,1775 VR2.1 ; C8.1@650,1984.5 854.57,1984.5 D2.1 ; C8.1@650,1985 650,2012.5 751,2113.5 C7.2
NetC11_1: C11.1 R9.A R12.B | length 423.7
  Top Layer w25: R9.A 2705,2790 R12.B 2883,2968 C11.1
NetC12_2: C12.2 C13.1 R8.A R13.B W1.2 | length 3057.9
  Bottom Layer w25: C12.2 3291.57,2705.28 R8.A
  Bottom Layer w100: W1.2 3148,3237 3220,3165 3335,3165 R13.B ; C12.2 3250,2900 R13.B ; C13.1 4503.15,2694.35 4325,2872.5 4325,2977.5 4282.5,3020 4177.5,3020 4120,3077.5 4120,3180 4085,3215 3565,3215 R13.B
NetC14_2: C14.2 U3.2 | length 285.7
  Top Layer w25: U3.2 2285,3295 2335,3345 C14.2@2485,3345
NetC15_1: C15.1 D9.1 U5.20 | length 402.3
  Top Layer w10: U5.20 3305,1275 3345,1315 3345,1470 3345,1555 3295,1605 D9.1
NetC16_1: C16.1 D7.1 U5.14 | length 822.3
  Top Layer w10: D7.1 2980,1560 C16.1 2990,1455 2990,1445 3005,1445 3098,1352 3098,1067 3190,975 U5.14
NetC17_2: C17.2 D8.1 U5.17 | length 588.5
  Top Layer w10: D8.1 3155,1560 C17.2@3155,1470 ; C17.2 3150,1435 3180,1405 3180,1155 3210,1125 U5.17
NetD1_2: D1.2 R4.2 T1.10 | length 358.6
  Top Layer w25: R4.2@1850,2300 1935,2300 ; D1.2@1935,2280 1935,2300 ; T1.10 1959.84,2479.84 1935,2455 1935,2300
NetD2_2: D2.2 R7.2 T1.9 | length 1370.9
  Top Layer w25: R7.2@895.79,2208.29 R7.2@900.79,2208.29 ; D2.2 R7.2@900.79,2208.29 ; T1.9 1958.17,2681.1 1505.5,2228.43 1505.5,2226.76 1487.03,2208.29 R7.2@900.79,2208.29
NetD3_3: D3.3 NTC1.1 | length 1409.9
  Top Layer w100: D3.3 5205.31,2819.69 NTC1.1
NetD4_1: D4.1 R12.A | length 263.6
  Top Layer w25: D4.1 2715,3390 2760,3345 R12.A
NetD4_2: D4.2 T1.2 U3.4 | length 1020.9
  Top Layer w25: U3.4 D4.2 2650,3195 2650,2905 2565,2820 2565,2630 2525.55,2590.55 T1.2
NetD5_2: D5.2 R15.1 | length 168.1
  Top Layer w10: D5.2 R15.1@2325,258.14
NetD6_2: D6.2 R14.1 | length 170
  Top Layer w10: D6.2 R14.1
NetD10_2: D10.2 R36.1 | length 166.9
  Top Layer w10: D10.2 R36.1
NetD11_2: D11.2 Q4.3 Q5.3 Q6.3 R19.1 R26.2 | length 5367.4
  Top Layer w10: R19.1 D11.2 2440,610 3100,-50 4250,-50 4425,125 4425,315 4410,300 v1(4400,300)
  Top Layer w50: v1(4400,825) 4400,916.54 Q5.3 4420,925 4520,825 v1(4500,825) ; v1(4400,1350) 4410,1350 4425,1365 4408.46,1381.54 Q4.3 4480,1450 4480,1445 4485,1450 v1(4500,1450)
  Bottom Layer w50: 4408.46,400 4420,400 4460,360 v1(4450,350) v1(4450,300)
  Bottom Layer w100: 4425,1365 4500,1290 v1@4500,945 ; v1@4477.5,1447.5 4563.15,1533.15 4563.15,1795 4621.3,1853.15 R26.2 ; 4490,425 4490,775
  other v1: 4500,300 4400,350 4500,350 4500,400 4450,825 4400,870.77 4450,875 4500,875 4500,925 4450,1350 4500,1350 4400,1400 4450,1400 4500,1400
NetF1_2: F1.2 NTC1.2 VR3.A | length 1187.6
  Top Layer w100: VR3.A 4512.4,3175 4787.4,3450 4870.28,3450 NTC1.2
NetP2_1: P2.1 R3.2 | length 519.6
  Top Layer w10: P2.1 70,1695.3 70,1455 R3.2
NetP2_2: P2.2 U1.3 | length 1048.1
  Top Layer w10: P2.2 162.5,1557.5 520,1200 U1.3
NetP5_1: P5.1 R45.2 | length 617.5
  Top Layer w10: P5.1 512.5,2750 R45.2@635,2750
NetP5_2: P5.2 U6.2 | length 764.2
  Top Layer w10: P5.2 424.7,2700 U6.2
NetP5_3: P5.3 R47.2 | length 544.7
  Top Layer w10: P5.3 336.91,2650 R47.2@635,2650
NetP5_4: P5.4 U6.4 | length 691.5
  Top Layer w10: P5.4 249.11,2600 U6.4
NetP5_5: P5.5 R48.2 | length 435.5
  Top Layer w10: P5.5 P5.5@163.68,2550 ; P5.5@201.18,2550 R48.2@635,2550
NetP5_6: P5.6 U6.6 | length 692.5
  Top Layer w10: P5.6 251.48,2500 U6.6
NetP5_7: P5.7 R49.2 | length 545.7
  Top Layer w10: P5.7 339.27,2450 R49.2@635,2450
NetP5_8: P5.8 U6.8 | length 765.2
  Top Layer w10: P5.8 427.07,2400 U6.8
NetPOT0_2: POT0.2 R27.2 | length 769.9
  Top Layer w10: R27.2 845,650 830,635 830,382.5 997,215.5 POT0.2
NetPOT1_2: POT1.2 R35.2 | length 1152.1
  Top Layer w10: R35.2 870,500 1157.5,212.5 1540,212.5 1685,67.5 POT1.2
NetQ1_1: Q1.1 R28.2 | length 977.3
  Top Layer w10: R28.2@3455,1430 3500,1430 3525,1405 v1(3525,1270) ; v1(4050,1225) 4150,1325 4191.54,1325 Q1.1
  Bottom Layer w10: v1(3525,1270) 3570,1225 v1(4050,1225)
NetQ2_1: Q2.1 R30.2 | length 1146.2
  Top Layer w10: R30.2@3465,1160 3480,1160 3495,1145 v1(3535,1145) ; v1(4115,1165) 4070,1120 4070,865 4110,825 Q2.1
  Bottom Layer w10: v1(3535,1145) 3555,1165 v1(4115,1165)
NetQ3_1: Q3.1 R32.2 | length 1439
  Top Layer w10: R32.2@3510,755 3510,170 3570,110 4101.54,110 4216.54,225 Q3.1
NetQ4_1: Q4.1 R29.2 | length 3794
  Top Layer w10: R29.2 2990,445 3350,85 4178,85 4288,195 4288,337 4255,370 4166,370 4096,440 4096,584.08 4170.92,659 4214,659 4285,730 4285,833.55 4260.88,857.67 4183.29,857.67 4108,932.96 4108,1078 4300,1270 4300,1400 4265,1435 4160,1435 4135,1460 4135,1615 4170,1650 Q4.1@4383.46,1650
NetQ5_1: Q5.1 R31.2 | length 3096.8
  Top Layer w10: R31.2 2995,360 3300,55 4190,55 4305,170 4305,344.04 4262.04,387 4197.96,387 4113,471.96 4113,577.04 4177.96,642 4242,642 4310,710 4310,832.59 4267.92,874.67 4190.33,874.67 4125,940 4125,1050 4200,1125 Q5.1
NetQ6_1: Q6.1 R33.2 | length 2351.7
  Top Layer w10: R33.2 3000,275 3245,30 4200,30 4325,155 4325,348.08 4269.08,404 4224.85,404 4135,493.85 4135,575 4160,600 Q6.1
NetR2_2: R2.2 U1.1 | length 110
  Top Layer w10: U1.1 R2.2
NetR3_1: R3.1 U1.4 | length 802.8
  Top Layer w10: R3.1 450,1150 U1.4
NetR14_2: R14.2 U2.2 | length 856.2
  Top Layer w10: R14.2@2125,340 v1(2125,825) ; v1(2125,1000) 2140,1015 U2.2
  Bottom Layer w10: v1(2125,825) v1(2125,1000)
NetR15_2: R15.2 U2.9 | length 1065.5
  Top Layer w10: R15.2 2325,1000 2385,1060 2385,1111.47 2415,1141.47 2415,1234.97 2425.03,1245 2480,1245 2490,1235 U2.9
NetR16_1: R16.1 R17.2 U3.1 | length 174.9
  Top Layer w25: R16.1 2170,3230 ; R17.2@2140,3285 2140,3260 2170,3230 ; U3.1 2170,3230
NetR16_2: R16.2 T1.4 | length 858.8
  Top Layer w25: R16.2@2060,3200 2060,3155 2073,3142 2473,3142 2524.8,3090.2 2524.8,2887.8 T1.4
NetR20_2: R20.2 R23.2 S0.1 S0.2 | length 778
  Top Layer w10: S0.2 S0.1 505,800 615,910 775,910 805,880 R20.2 ; R20.2@810,850 R23.2@880,850
NetR21_1: R21.1 U4.15 | length 78.1
  Top Layer w10: U4.15 R21.1
NetR22_1: R22.1 U4.13 | length 78.1
  Top Layer w10: U4.13 R22.1
NetR23_1: R23.1 U4.1 | length 93.1
  Top Layer w10: R23.1 U4.1
NetR24_1: R24.1 U4.3 | length 93.1
  Top Layer w10: R24.1 U4.3
NetR24_2: R24.2 R25.2 S1.1 S1.2 | length 1041.3
  Top Layer w10: S1.2 S1.1 655,460 R25.2 R24.2
NetR27_1: R27.1 U4.5 | length 93.1
  Top Layer w10: R27.1 U4.5
NetR28_1: R28.1 U5.19 | length 269.9
  Top Layer w10: U5.19 3395,1225 3455,1285 R28.1
NetR29_1: R29.1 U5.10 | length 386.2
  Top Layer w10: R29.1 2860,810 U5.10@2875,825
NetR30_1: R30.1 U5.16 | length 192.1
  Top Layer w10: U5.16 3460,1075 R30.1
NetR31_1: R31.1 U5.9 | length 601.1
  Top Layer w10: R31.1 2815,405 2815,845 2845,875 U5.9
NetR32_1: R32.1 U5.13 | length 298.6
  Top Layer w10: U5.13 3465,925 3510,880 R32.1
NetR33_1: R33.1 U5.8 | length 786.8
  Top Layer w10: R33.1 2775,360 2775,885 2815,925 U5.8
NetR35_1: R35.1 U4.7 | length 93.1
  Top Layer w10: R35.1 U4.7
NetR40_1: R40.1 U6.11 | length 93.1
  Top Layer w10: U6.11 R40.1
NetR43_1: R43.1 U6.9 | length 93.1
  Top Layer w10: U6.9 R43.1
NetR44_1: R44.1 U6.13 | length 93.1
  Top Layer w10: U6.13 R44.1
NetR45_1: R45.1 U6.1 | length 103.1
  Top Layer w10: R45.1 U6.1
NetR47_1: R47.1 U6.3 | length 103.1
  Top Layer w10: R47.1 U6.3
NetR48_1: R48.1 U6.5 | length 103.1
  Top Layer w10: R48.1 U6.5
NetR49_1: R49.1 U6.7 | length 103.1
  Top Layer w10: R49.1 U6.7
NEU: D3.2 P3.1 VR3.B W1.1 | length 2595.1
  Top Layer w100: W1.1 3122,3515 3330,3515 P3.1 3465,3285 3600,3150 ; D3.2@4004.84,2605 D3.2 3940.16,2550 3600,2550 3600,3150 ; VR3.B 4250,3200 3650,3200 3600,3150
"OPEN/CLOSE DOOR": R18.1 R21.2 R22.2 U2.3 | length 1173.1
  Top Layer w8: R22.2@1460,700 R21.2@1460,800
  Top Layer w10: R22.2@1460,700 1470,690 R18.1 1915,690 2190,965 U2.3
PGC: P1.5 U2.18 | length 245.9
  Top Layer w8: P1.5 2190,1620 U2.18
PGD/RAMP: P1.4 R38.2 U2.19 U4.9 | length 2315.2
  Top Layer w8: U4.9 1248.74,500 1190,558.74 1190,860 1320,990 1905.91,990 1936,1020.09 1936,1049.91 1885.91,1100 v1(1880,1100) ; P1.4 2045,1665 2095,1665 2140,1620 U2.19 2140,1365 v1(2050,1275)
  Top Layer w10: U4.9 R38.2
  Bottom Layer w8: v1(1880,1100) 1875,1100 v1(2050,1275)
PWM1: U2.5 U5.4 | length 771.3
  Top Layer w8: U2.5 2290,1250 2320,1280 2692.43,1280 2701.43,1271 2731.12,1271 2761,1241.12 2761,1199 2835,1125 U5.4
PWM2: U2.7 U5.5 | length 678.5
  Top Layer w8: U2.7 2390,1245 2406,1261 2690.21,1261 2695.21,1256 2724.91,1256 2746,1234.91 2746,1184 2855,1075 U5.5
PWM4: U2.15 U5.6 | length 1100.2
  Top Layer w10: U2.15 2340,1510 2515,1335 2815,1335 2847,1303 2946.21,1303 2975,1274.21 2975,1045 2955,1025 U5.6
SCL: R11.1 U2.11 | length 192.4
  Top Layer w10: R11.1 2540,1715 U2.11
SDA: R10.1 U2.13 | length 114.1
  Top Layer w10: R10.1 2440,1665 U2.13
SPEED: R34.2 U2.14 U4.11 | length 2361.9
  Top Layer w7: R34.2 1429.95,649.95 1944.95,649.95 2089.5,794.5 2089.5,839.7 2110.3,860.5 2155.5,860.5 2363.5,1068.5 2363.5,1234.35 2357.35,1240.5 2322.65,1240.5 2313.5,1231.35 2313.5,1145.65 2307.35,1139.5 2272.65,1139.5 2263.5,1148.65 2263.5,1234.35 2216.5,1281.35 2216.5,1609.35 2237.15,1630 2370,1630 2390,1610 U2.14
  Top Layer w10: U4.11 R34.2
VPP/AUX0: P1.1 R46.2 U2.4 U6.15 | length 2689
  Top Layer w7: P1.1 1715,1815 1785,1815 1805,1795 1805,1380 1860,1325 1900,1325 1915,1310 1915,1167.15 1930.65,1151.5 2041.7,1151.5 2065.5,1175.3 2065.5,1233.35 2092.15,1260 2210,1260 2240,1230 U2.4
  Top Layer w10: U6.15 R46.2 1175,2665 1190,2650 1310,2650 1345,2615 1345,2420 v1(1400,2365) ; v1(1550,2210) 1503,2163 1503,2007 1655,1855 P1.1
  Bottom Layer w10: v1(1400,2365) 1550,2215 v1(1550,2210)
pads on no net: P1.6 T1.3 T1.6 U3.3
copper on no net: | length 520
  Bottom Layer w10: 2325,-190 2325,-35 2430,-35 2430,-190 2325,-190

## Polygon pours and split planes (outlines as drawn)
NetD11_2 on Top Layer "Top Layer-NetQ4_3" (solid, pour order 20): 4375,1475 4550,1475 4550,1330.51 4544.49,1325 4375,1325
NetD11_2 on Top Layer "Top Layer-NetQ4_3" (solid, pour order 21): 4375,950 4550,950 4550,805.51 4544.49,800 4375,800
NetD11_2 on Top Layer "Top Layer-NetQ4_3" (solid, pour order 22): 4375,425 4550,425 4550,280.51 4544.49,275 4375,275
+VBUS on Top Layer "Top Layer-+VBUS" (solid, pour order 12): 3600,150 4000,150 4000,2300 4075,2375 4075,2450 3600,2450
DGND on Top Layer "Top Layer-DGND" (solid, pour order 14): 1050,3500 2000,3500 2000,2450 2075,2375 2550,2375 2550,1975 2600,1925 2825,1925 2825,1675 3200,1675 3200,-100 2000,-100 2000,450 1300,450 1300,1025 1050,1275
AGND on Top Layer "Top Layer-AGND" (solid, remove dead copper, pour order 16): 5400,2000.86 4525,2000 4100,2425 3400,2425 3400,2100 2625,2100 2625,2500 2400,2500 2400,3393 3763.55,3399.6 5400,3525
ISOGND on Top Layer "Bottom Layer-ISOGND" (solid, pour order 18): 50,3550 950,3550 950,1225 1162.5,1012.35 1162.5,387.5 1900,387.5 1900,-150 50,-150
DGND on Bottom Layer "Bottom Layer-DGND" (solid, pour order 13): 1050,3500 2000,3500 2000,2450 2075,2375 2550,2375 2550,1975 2600,1925 2825,1925 2825,1675 3200,1675 3200,-100 2000,-100 2000,450 1300,450 1300,1025 1050,1275
NetD11_2 on Bottom Layer "Bottom Layer-NetQ4_3" (solid, pour order 19): 4400,-100 4700,-100 4700,1650 5450,1650 5450,1900 4400,1900
AGND on Bottom Layer "Bottom Layer-AGND" (solid, remove dead copper, pour order 15): 5400,2000.86 4524.14,2000.86 4430,2095 3525,2095 3525,2100 2625,2100 2625,2500 2400,2500 2400,3550 5400,3550
ISOGND on Bottom Layer "Bottom Layer-ISOGND" (solid, pour order 17): 50,3550 965,3550 965,1230 1162.5,1025 1162.5,387.5 1900,387.5 1900,-150 50,-150

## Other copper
Bottom Layer:
  text ".Rev" at 2405,-145 h80
  text ".Drawing Number" at 2780,-150 h40

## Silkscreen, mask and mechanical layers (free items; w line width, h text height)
Top Overlay:
  region: 1650,1685 1685,1650 1610,1650
  lines w8: 325,1650 450,1650 510,1710 510,1740 450,1800 437.5,1800 425,1812.5 400,1787.5 375,1812.5 362.5,1800 350,1787.5 337.5,1800 325,1800 ; 325,2125 450,2125 450,2200 ; 325,2275 337.5,2275 350,2262.5 362.5,2275 375,2287.5 400,2262.5 425,2287.5 437.5,2275 450,2275 450,2225 ; 325,2400 450,2400 450,2475 ; 325,2550 337.5,2550 350,2537.5 362.5,2550 375,2562.5 400,2537.5 425,2562.5 437.5,2550 450,2550 450,2500 ; 325,2675 450,2675 450,2750 ; 325,2825 337.5,2825 350,2812.5 362.5,2825 375,2837.5 400,2812.5 425,2837.5 437.5,2825 450,2825 450,2775 ; 325,2950 450,2950 450,3025 ; 325,3100 337.5,3100 350,3087.5 362.5,3100 375,3112.5 400,3087.5 425,3112.5 437.5,3100 450,3100 450,3050 ; 425,2200 475,2200 ; 425,2475 475,2475 ; 425,2750 475,2750 ; 425,3025 475,3025 ; 485,1700 485,1685 500,1685 ; 487.5,2187.5 512.5,2162.5 ; 487.5,2225 512.5,2200 ; 487.5,2462.5 512.5,2437.5 ; 487.5,2500 512.5,2475 ; 487.5,2737.5 512.5,2712.5 ; 487.5,2775 512.5,2750 ; 487.5,3012.5 512.5,2987.5 ; 487.5,3050 512.5,3025 ; 500,2162.5 512.5,2162.5 ; 500,2200 512.5,2200 ; 500,2437.5 512.5,2437.5 ; 500,2475 512.5,2475 ; 500,2712.5 512.5,2712.5 ; 500,2750 512.5,2750 ; 500,2987.5 512.5,2987.5 ; 500,3025 512.5,3025 ; 510,1670 510,1770 ; 512.5,2212.5 512.5,2200 ; 512.5,2487.5 512.5,2475 ; 512.5,2762.5 512.5,2750 ; 512.5,3037.5 512.5,3025 ; 1110,360 ccw(c1005,195) 840,300 ; 1115,365 ccw(c1010,195) 840,300 ; 1120,370 ccw(c1015,195) 840,300 ; 1125,375 ccw(c1020,195) 840,300 ; 1800,335 ccw(c1695,170) 1530,275 ; 1805,340 ccw(c1700,170) 1530,275 ; 1810,345 ccw(c1705,170) 1530,275 ; 1815,350 ccw(c1710,170) 1530,275 ; 450,2200 475,2225 425,2225 450,2200 ; 450,2475 475,2500 425,2500 450,2475 ; 450,2750 475,2775 425,2775 450,2750 ; 450,3025 425,3050 475,3050 450,3025 ; 512.5,2162.5 512.5,2175 512.5,2162.5 ; 512.5,2437.5 512.5,2450 512.5,2437.5 ; 512.5,2712.5 512.5,2725 512.5,2712.5 ; 512.5,2987.5 512.5,3000 512.5,2987.5 ; 840,300 cw(c987.5,197.5) 1090,345 1100,355 1105,355 ; 840,300 cw(c993.65,196.35) 1097.3,350 1102.3,355 1105,355 ; 840,300 cw(c1000,195) 1105,355 ; 840,300 cw(c1025,195) 1130,380 ; 1105,355 1130,380 ; 1130,380 1130,380 ; 1130,380 1130,380 ; 1530,275 cw(c1715,170) 1820,355 ; 1530,275 cw(c1690,170) 1795,330 ; 1530,275 cw(c1683.65,171.35) 1787.3,325 1792.3,330 1795,330 ; 1530,275 cw(c1677.5,172.5) 1780,320 1790,330 1795,330 ; 1795,330 1820,355 ; 1820,355 1820,355 ; 1820,355 1820,355
  lines w10: 965,3575 965,1230 1165,1030 1165,395 1970,395 1970,-170 ; 2700,-175 2700,1940 5025,1940
  text "INSTALL W1 for 115V IN" at 2140,3540 h45
  text "ISOLATED" at 337.5,3237.5 h80
  text "AUX0" at 334,3131 h45
  text "115~230V AC" at 3050,3112.5 h85
  text "DIGITAL" at 612.5,3087.5 h45
  text "I/O" at 612.5,3000 h45
  text "AUX1" at 327,2856 h45
  text "AUX2" at 318,2577 h45
  text "AUX3" at 338,2301 h45
  text "H" at 4075,2100 h200
  text "DRIVER STAGE" at 3525,1850 h45
  text "AUX4" at 341,1838 h45
  text "U" at 5285,1385 h100
  text "V" at 5020,995 h100
  text "W" at 5260,575 h100
  text "MOTOR" at 5125,460 h60
  text "OUT" at 5180,370 h60
  text "3/4 HP" at 5125,275 h45
  text "H" at 4500,100 h200
  text "DANGER HIGH VOLTAGE" at 4150,50 h45
  text "M" at 2725,-75 h500
  text "TRIP" at 2005,-125 h45
  text "MOTOR" at 2235,-125 h45
  text "PWR" at 2525,-125 h45
  text "AC INDUCTION MOTOR 3-PHASE CONTROLLER Rev C" at 3350,-175 h45
CropMarks 9:
  lines w10: 0,300 0,-200 500,-200 ; 0,3100 0,3600 ; 5000,-200 5500,-200 5500,300 ; 5000,3600 5500,3600 5500,3100 ; 0,3600 500,3600 0,3600
BoardOutline 10:
  the board outline again, w10
SheetFormat 16:
  lines w5: -2100,-2525 -1900,-2525 ; -2100,-150 -1900,-150 ; -2100,2225 -1900,2225 ; 75,-200 275,-200 ; 400,-4900 400,-4700 ; 400,4400 400,4600 ; 2900,-4900 2900,-4700 ; 2900,4400 2900,4600 ; 5400,-4900 5400,-4700 ; 5400,4400 5400,4600 ; 7900,-4900 7900,-4700 ; 7900,4400 7900,4600 ; 8200,-4400 12700,-4400 ; 8200,-4100 12700,-4100 ; 8200,-3800 9700,-3800 ; 9700,-4700 9700,-4100 9700,-3500 ; 10400,-4900 10400,-4700 ; 10400,4400 10400,4600 ; 11800,-4700 11800,-4100 ; 12700,-2525 12900,-2525 ; 12700,-150 12900,-150 ; 8200,-4700 6800,-4700 6800,-3500 8200,-3500 ; 8200,-4700 12700,-4700 ; 8200,-4700 8200,-3500 ; 8200,-3500 9700,-3500 ; 9700,-3500 12700,-3500 12700,-4700 ; 12700,-4700 12700,4400 -1900,4400 -1900,-4700 12700,-4700 ; -2100,-4900 -2100,4600 12900,4600 12900,-4900 -2100,-4900
  lines w10: 8805,2280 12680,2280 ; 8825,3800 8825,4000 ; 8825,4200 12700,4200 ; 8825,4400 8825,4000 ; 9075,3800 9075,4000 9075,4400 ; 9750,3800 9750,4000 9750,4400 ; 10675,-1225 10725,-1225 ; 11950,3800 11950,4000 11950,4400 ; 12700,4000 8825,4000 ; 0,-200 5500,-200 5500,3600 0,3600 0,-200
  text "1" at -868.66,4470 h70
  text "2" at 1627,4470 h70
  text "3" at 4116.34,4470 h70
  text "4" at 6623.01,4470 h70
  text "5" at 9122,4470 h70
  text "6" at 11627,4470 h70
  text "Rev" at 8850,4275 h130
  text "ECO No." at 9200,4275 h130
  text "Description" at 10575,4275 h130
  text "Date" at 12200,4275 h130
  text "A" at 8900,4100 h70
  text "B" at 8900,3900 h70
  text "A" at -2025,3327 h70
  text "B" at -2025,947 h70
  text "C" at -2025,-1428 h70
  text "C" at 12775,-1428 h70
  text "Rev" at 10900,-1975 h130
  text "ENGINEER:" at 8250,-3600 h45
  text "TITLE:" at 9750,-3600 h45
  text ".Engineer" at 8275,-3750 h130
  text "D" at -2025,-3798 h70
  text "D" at 12775,-3798 h70
  text "PCB DESIGNER:" at 8250,-3895 h45
  text ".Title" at 10150,-3925 h180
  text ".Designer" at 8275,-4050 h130
  text "DATE:" at 8250,-4200 h45
  text "FabDwg No.:" at 9750,-4200 h45
  text "REV:" at 11850,-4200 h45
  text "M" at 6930,-4210 h600
  text ".Rev" at 12075,-4325 h180
  text ".Print_Date" at 8275,-4350 h130
  text ".FabDwg_Num" at 10150,-4350 h130
  text "2355 W. Chandler Blvd" at 6900,-4435 h130
  text "FILE NAME:" at 8250,-4500 h45
  text "AssyDwg No.:" at 9750,-4500 h45
  text "SCALE:" at 11850,-4500 h45
  text "Chandler, AZ 85224" at 6985,-4575 h130
  text ".Pcb_File_Name_No_Path" at 8250,-4650 h130
  text ".AssyDwg_Num" at 10150,-4650 h130
  text ".Print_Scale" at 11950,-4650 h130
  text "1" at -868.66,-4830 h70
  text "2" at 1627,-4830 h70
  text "3" at 4116.34,-4830 h70
  text "4" at 6623.01,-4830 h70
  text "5" at 9122,-4830 h70
  text "6" at 11627,-4830 h70
Drill Drawing:
  lines w10: 0,-200 5500,-200 5500,3600 0,3600 0,-200 ; 9650,-1125 9775,-1125 9775,-1000 9650,-1000 9650,-1125 ; 9650,-825 9775,-825 9775,-700 9650,-700 9650,-825 ; 9650,-625 9775,-625 9775,-500 9650,-500 9650,-625 ; 9650,-425 9775,-425 9775,-300 9650,-300 9650,-425 ; 9650,425 9650,550 9775,550 9775,425 9650,425 ; 9975,-2000 10825,-2000 10825,-1875 9975,-1875 9975,-2000 ; 10375,425 10500,425 10500,550 10375,550 10375,425 ; 10950,425 11075,425 11075,550 10950,550 10950,425 ; 10975,-175 11275,-175 11275,-50 10975,-50 10975,-175 ; 10975,25 11275,25 11275,150 10975,150 10975,25 ; 10975,225 10975,350 11275,350 11275,225 10975,225 ; 11125,-2000 11275,-2000 11275,-1875 11125,-1875 11125,-2000
  text "Notes:" at 8950,1125 h160
  text "This PCB to be manufactured to meet all acceptance levels" at 9100,950 h130
  text "of a CLASS 2 PCB per ANSI/IPC-A-600G." at 9125,825 h130
  text "Material:  Isola PCL370HR FR-4 or equivalent." at 9125,650 h130
  text "Multilayer" at 9800,450 h130
  text "2" at 10425,450 h60
  text "Layers" at 10525,450 h130
  text "Controlled Impedance" at 11100,450 h130
  text "Cu weight external layers" at 9625,250 h130
  text "1oz" at 11025,250 h60
  text "Cu weight internal layers" at 9625,50 h130
  text "Finished overall thickness" at 9625,-150 h130
  text "0.062" at 11000,-150 h60
  text "Finish:" at 9125,-400 h130
  text "X" at 9700,-400 h60
  text "Immersion Gold" at 9800,-400 h130
  text "Immersion Tin" at 9800,-600 h130
  text "Soldermask over bare copper (SMOBC) with" at 9800,-800 h130
  text "Hot-Air-Leveled-Solder" at 9800,-925 h130
  text "If edge connector fingers are present, plate" at 9800,-1100 h130
  text "with Nickel/Gold > 20 microinches Gold" at 9800,-1225 h130
  text "Soldermask:  Dynachem EPIC 200 LPI or equivalent." at 9125,-1425 h130
  text "Soldermask Color:  Green" at 9125,-1575 h130
  text "Silkscreen Color:  White" at 9125,-1725 h130
  text "Artwork Set No." at 9125,-1975 h130
  text ".Artwork_Num" at 10000,-1975 h130
  text ".Artwork_Rev" at 11125,-1975 h130
  text "All holes to be located by the NC Drill file." at 9125,-2200 h130
  text "Indicate Country where PCB was fabricated on the" at 9125,-2350 h130
  text "side indicated." at 9125,-2475 h130
  text "Any deviation from the above specs must be approved" at 9125,-2625 h130
  text "by Microchip." at 9125,-2750 h130

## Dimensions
0,-200 to 0,3600 on Drill Drawing
0,-200 to 5500,-200 on Drill Drawing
